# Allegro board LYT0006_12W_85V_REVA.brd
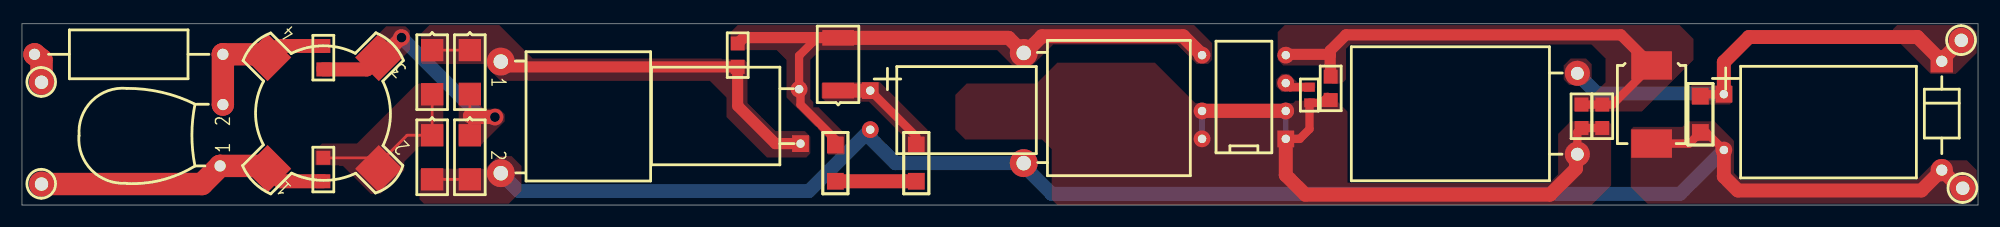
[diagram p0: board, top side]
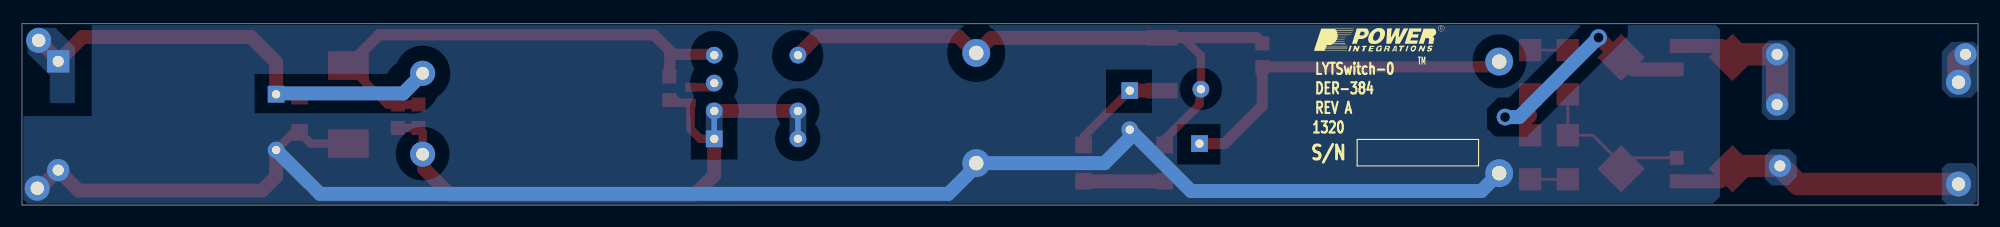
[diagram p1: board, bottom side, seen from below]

Outline 178.05 x 16.5 mm; copper layers: TOP, BOTTOM. Coordinates in mm from the lower left corner of the outline.
Outline path: 0,16.5 178.05,16.5 178.05,0 0,0 0,16.5

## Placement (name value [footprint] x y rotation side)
C1  100 nF  [PINPCAPRAD500X260400040H]  43.56 13.09 270 top
C2  330 nF  [PI_NP_CAPRAD512X299LS394D040_H]  91.19 13.85 270 top
C3  100 nF  [PISMC0603]  117.2 10.72 270 top
C4  22 uF  [PISMC0805]  119.13 11.69 270 top
C5  68 uF  [PIPOLCAPCLYD395X630LS200030H]  154.91 10.09 270 bottom
C6  1.0 uF  [PIPOLCAPCLYD320LS140030H]  77.22 8.64 270 top
D1  S1ML  [PISMDSMA]  37.34 14.1 270 top
D2  S1ML  [PISMDSMA]  40.77 14.1 270 top
D3  S1ML  [PISMDSMA]  37.34 6.35 270 top
D4  S1ML  [PISMDSMA]  40.77 6.35 270 top
D5  STTH2R06S  [PISMDO214AB12]  148.34 12.7 270 top
D6  DL4005-13-F  [PISMDMLL4112]  74.3 10.42 90 top
J1  PCB Terminal 22 AWG  [PI_HOLE_22AWG]  1.78 1.91 0 top
J2  PCB Terminal 22 AWG  [PI_HOLE_22AWG]  1.78 11.18 0 top
J3  PCB Terminal 22 AWG  [PI_HOLE_22AWG]  176.53 14.99 0 top
J4  PCB Terminal 22 AWG  [PI_HOLE_22AWG]  176.66 1.53 0 top
L1  10 mH  [PI_SM_IND_RENCO_RL9250]  22.35 3.31 135 top
L2  10 mH  [PI_CHOKE_450HX375LS197D030_H]  71.25 5.59 90 top
L3  3.3mh  [PI_CHOKE_710HX450LS290D046_H]  141.58 4.63 90 top
NOREF  -  []  0.64 0 90 top
NOREF#2  -  []  0 16.5 0 top
NOREF#3  -  []  -150.78 54.24 0 top
NOREF#4  -  []  -228.6 -144.78 0 top
NOREF#5  -  []  60.45 13.97 180 bottom
R1  4.7 k  [PISMR0805]  65.15 12.58 90 top
R2  30.1  [PISMR0805]  141.96 7.01 90 top
R3  30.1  [PISMR0805]  143.84 7.01 90 top
R4  180 k  [PISMR1206]  74.04 5.47 270 top
R5  180 k  [PISMR1206]  81.41 2.16 90 top
R6  22 k  [PISMR0805]  27.43 2.16 90 top
R7  1 M  [PISMR1206]  152.78 9.91 270 top
R8  22 k  [PISMR0805]  27.43 14.48 270 top
RF1  4.7  [PI12WVRESD180LS200D040]  18.29 13.72 180 top
RV1  275 Vac  [PI_DISC_354X220_LS220X10_040_H]  18.03 3.56 90 top
U1  LYT0006PN  [PIICDIP8B]  115.04 6.02 90 top
VR1  1N4764A  [PIDV200X110X040DO41]  174.75 13.09 270 top

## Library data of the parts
C1 = CAP NP: alternate symbols: (pinpcaprad500x260400040h)
C2 = CAP NP: alternate symbols: (pi_np_caprad512x299ls394d040_h)
C3 C4 = CAP NP
C5 = CAP POL: alternate symbols: (pipolcapclyd395x630ls200030h)
C6 = CAP POL: alternate symbols: (pipolcapclyd320ls140030h)
D1-D6 = DIODE
J1-J4 = TERM_1PIN
L1 = INDUCTOR_4P_revD
L2 L3 = INDUCTOR
R1-R8 = R
RF1 = R: alternate symbols: (pi12wvresd180ls250d040,pi12wresd180ls675d040)
RV1 = VARISTOR
U1 = LNK30X_HS_0
VR1 = DIODE_ZENER: alternate symbols: (pidax475x125040do41,pidv200x110x040do41wbead,pidax390x125040do41)

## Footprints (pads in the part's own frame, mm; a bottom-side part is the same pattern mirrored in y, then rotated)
PI12WVRESD180LS200D040
  round 2.032 hole 1.016: 1(0,0) 2(17.145,0)
PI_CHOKE_450HX375LS197D030_H
  rect 1.524x1.524 hole 0.762: 1(0,0.381)
  round 1.524 hole 0.762: 2(4.953,0.508)
PI_CHOKE_710HX450LS290D046_H
  round 2.286 hole 1.168: 1(0,0) 2(7.366,0)
PI_DISC_354X220_LS220X10_040_H
  round 2.032 hole 1.016: 1(0,0) 2(5.588,-0.254)
PI_HOLE_22AWG
  round 2.286 hole 1.219: 1(0,0)
PI_NP_CAPRAD512X299LS394D040_H
  round 2.54 hole 1.321: 1(0,0) 2(10.033,0)
PI_SM_IND_RENCO_RL9250
  rect 3.048x3.048 smd: 1(0,0) 2(-7.163,-7.163) 3(0,-14.326) 4(7.163,-7.163)
PIDV200X110X040DO41
  rect 2.032x2.032 hole 1.016: 1(0,0)
  round 2.032 hole 1.016: 2(9.906,0)
PIICDIP8B
  rect 1.524x1.524 hole 0.762: 1(0,0)
  round 1.524 hole 0.762: 2(2.54,0) 3(5.08,0) 4(7.62,0) 5(7.62,7.62) 7(2.54,7.62) 8(0,7.62)
PINPCAPRAD500X260400040H
  round 2.54 hole 1.321: 1(0.025,0.025) 2(10.185,0.025)
PIPOLCAPCLYD320LS140030H
  rect 1.524x1.524 hole 0.762: 1(-1.778,0)
  round 1.524 hole 0.762: 2(1.778,0)
PIPOLCAPCLYD395X630LS200030H
  rect 1.524x1.524 hole 0.762: 1(0,0)
  round 1.524 hole 0.762: 2(5.08,0)
PISMC0603
  rect 0.813x0.965 smd: 1(0,0) 2(1.422,0)
PISMC0805
  rect 1.27x1.27 smd: 1(0,0) 2(2.134,0)
PISMDMLL4112
  rect 1.422x2.896 smd: 1(0,0) 2(4.801,0)
PISMDO214AB12
  rect 2.591x3.708 smd: 1(0,0) 2(7.112,0)
PISMDSMA
  rect 2.032x2.032 smd: 1(0,0) 2(4.013,0)
PISMR0805
  rect 1.27x1.27 smd: 1(0,0) 2(2.134,0)
PISMR1206
  rect 1.524x1.524 smd: 1(0,0) 2(3.302,0)

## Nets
SOURCE: C3.2 C4.2 L3.1 R2.1 R3.1 U1.1(SOURCE) U1.2 U1.7 U1.8
N40967: C1.1 D1.1 D2.1 L2.1 R1.1
N41017: C1.2 C2.2 C5.2 C6.2 D3.2 D4.2 D5.2 J4.1 R7.2 VR1.2
N41033: C2.1 D6.2 L2.2 R1.2 R4.1 U1.5(D)
N41049: C4.1 D5.1 R2.2 R3.2 U1.4(FB)
N41137: C5.1 J3.1 L3.2 R7.1 VR1.1
N41161: J1.1 L1.1 R6.1 RV1.1
N41165: L1.4 R8.1 RF1.1 RV1.2
N41233: C3.1 U1.3(BP)
N41297: J2.1 RF1.2
N42430: D2.2 D4.1 L1.3 R8.2
N42434: D1.2 D3.1 L1.2 R6.2
N45514: R4.2 R5.1
N45535: C6.1 D6.1 R5.2

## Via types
v1: diameter 1.524, hole 0.889, TOP to BOTTOM, 2 vias

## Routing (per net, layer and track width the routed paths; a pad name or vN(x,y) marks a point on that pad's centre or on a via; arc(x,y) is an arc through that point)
SOURCE: length 57.6
  TOP w0.508: C4.2 118.87,9.3 118.31,9.3
  TOP w0.762: L3.1 141.58,6.63 R2.1 R3.1 ; 118.85,9.84 118.31,9.3 C3.2 117.2,6.91 116.31,6.02 U1.1
  TOP w1.27: L3.1 141.45,4.5 141.45,3.31 139.09,0.94 116.81,0.94 115.04,2.72 U1.1 ; U1.7 U1.2
  BOTTOM w0.508: U1.8 U1.7 ; U1.1 U1.2
N40967: length 35.9
  TOP w0.254: D1.1 D2.1
  TOP w0.762: 44.07,12.58 C1.1
  TOP w1.016: 44.07,12.58 R1.1 65.15,9.02 68.58,5.59 L2.1
N41017: length 156.2
  TOP w0.254: D3.2 D4.2
  TOP w0.762: C5.2 153.31,6.61 R7.2 151.76,5.59 D5.2
  TOP w1.27: C5.2 154.91,2.6 156.18,1.33 172.9,1.33 174.75,3.18 176.4,1.53 J4.1
  BOTTOM w1.27: C5.2 150.93,1.02 93.73,1.02 91.19,3.56 C2.2 79.5,3.81 77.22,6.1 C6.2 71.63,1.27 45.21,1.27 C1.2
N41033: length 56.2
  TOP w0.762: 72.39,15.24 70.74,13.59 L2.2 70.87,10.42 70.87,9.15 74.04,5.97 R4.1
  TOP w1.016: R1.2 65.68,15.24 74.27,15.24 D6.2
  TOP w1.27: D6.2 89.81,15.22 C2.1 91.31,13.85 92.84,15.37 105.69,15.37 U1.5
N41049: length 45.4
  TOP w0.762: D5.1 144.78,9.15 R3.2 R2.2
  TOP w1.016: C4.1 119.13,12.58 119.08,12.62 119.08,13.64 ; U1.4 115.11,13.72 119,13.72 119.08,13.64 ; D5.1 145.54,15.5 120.52,15.5 119.08,14.06 119.08,13.64
N41137: length 43.6
  TOP w0.762: R7.1 152.96,10.09 C5.1
  TOP w1.27: C5.1 154.91,13.01 157.2,15.3 172.54,15.3 VR1.1 174.75,13.21 J3.1
  BOTTOM w1.27: L3.2 141.58,11.94 143.36,10.16 154.84,10.16 C5.1
N41161: length 26.9
  TOP w1.27: L1.1 23.5,2.16 R6.1
  TOP w2.032: J1.1 16.38,1.91 RV1.1 22.1,3.56 L1.1
N41165: length 14.3
  TOP w1.27: L1.4 23.4,14.48 R8.1
  TOP w2.032: L1.4 22.07,13.72 RF1.1 RV1.2
N41233: length 2.3
  TOP w0.762: C3.1 115.42,10.72 U1.3
N41297: length 2.8
  TOP w2.032: J2.1 1.78,13.21 RF1.2
N42430: length 25.9
  TOP w0.254: D2.2 D4.1
  TOP w1.27: v1(43.05,8.01) 40.89,8.01 40.77,8.13 ; v1(34.54,15.24) 32.74,13.44 L1.3 31.39,12.35 R8.2
  BOTTOM w1.27: v1(43.05,8.01) 41.78,8.01 v1(34.54,15.24)
N42434: length 15.6
  TOP w0.254: R6.2 31.49,4.3 L1.2 32.48,3.78 35.05,6.35 D3.1 D1.2
N45514: length 7.4
  TOP w1.27: R4.2 R5.1
N45535: length 9.6
  TOP w0.762: C6.1 81.41,6.23 R5.2
  TOP w1.27: C6.1 D6.1

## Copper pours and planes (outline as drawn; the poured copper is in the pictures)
SOURCE on TOP: 115.7,9.28 106.81,9.28 103.12,12.96 94.23,12.96 92.33,11.05 85.98,11.05 84.96,10.04 84.96,6.86 85.85,5.97 92.84,5.97 93.73,5.08 93.73,0.51 94.23,0 119.13,0 120.65,1.53 120.65,8.51 118.87,10.29 118.49,10.29 117.86,9.66 116.08,9.66
SOURCE on TOP: 144.4,7.62 140.97,7.62 139.83,6.48 139.83,2.8 139.06,2.04 120.65,2.04 120.52,2.16 119.38,2.16 118.62,1.4 118.62,0.51 119.13,0 142.88,0 144.65,1.78 144.65,7.37
SOURCE on BOTTOM: 115.49,9.3 114.66,9.3 114.27,8.92 114.27,5.26 115.77,5.26 115.8,5.29 115.8,9
SOURCE on BOTTOM: 107.87,9.25 107.04,9.25 106.65,8.87 106.65,5.69 107.04,5.31 107.72,5.31 108.18,5.77 108.18,8.95
N40967 on TOP: 36.32,12.96 36.32,15.63 37.08,16.39 43.43,16.39 46.48,13.34 65.66,13.34 66.04,12.96 66.04,9.28 68.58,6.74 71.25,6.74 71.75,6.23 71.75,4.7 71.37,4.32 67.82,4.32 64.14,8.01 64.14,9.78 62.61,11.31 43.56,11.31 42.04,12.83 36.45,12.83
N41017 on TOP: 146.43,1.66 146.43,6.86 146.69,7.12 151.13,7.12 151.64,7.62 154.05,7.62 155.83,5.85 155.83,2.93 156.46,2.29 172.47,2.29 174.24,4.07 177.04,4.07 177.93,3.18 177.93,0.77 177.29,0.13 147.96,0.13
N41017 on TOP: 36.32,3.31 42.16,3.31 43.31,4.45 44.58,4.45 45.47,3.56 45.47,1.27 44.32,0.13 36.58,0.13 36.2,0.51 36.2,3.18
N41017 on BOTTOM: 24.13,0.13 23.5,0.77 23.5,16.01 23.88,16.39 31.88,16.39 31.88,15.37 41.02,6.23 43.94,6.23 44.7,6.99 44.7,8.77 43.69,9.78 42.67,9.78 36.07,16.39 90.46,16.39 91.19,11.2 91.92,16.39 171.7,16.39 171.7,8.11 177.93,8.11 177.93,0.51 177.55,0.13 ; 9 cut-outs
N41033 on TOP: 64.52,14.1 64.52,15.75 65.15,16.39 106.68,16.39 108.33,14.74 108.33,13.21 107.95,12.83 106.93,12.83 105.16,14.61 93.85,14.61 91.82,12.58 90.3,12.58 88.77,14.1 72.64,14.1 71.75,13.21 71.75,9.66 74.93,6.48 74.93,4.7 74.8,4.58 73.41,4.58 73.28,4.7 73.28,6.1 69.6,9.78 69.6,13.21 68.71,14.1
N41049 on TOP: 114.3,13.21 114.3,15.75 114.94,16.39 150.88,16.39 152.15,15.12 152.15,13.21 147.45,8.51 141.35,8.51 141.22,8.64 141.22,9.91 141.48,10.16 143.13,10.16 144.15,11.18 144.15,13.34 142.88,14.61 120.9,14.61 120.52,14.23 120.52,11.43 120.14,11.05 118.49,11.05 118.49,12.32 118.11,12.7 114.81,12.7
N41137 on TOP: 170.31,16.01 170.69,16.39 177.29,16.39 177.93,15.75 177.93,13.85 176.02,11.94 173.74,11.94 170.31,15.37
N41137 on TOP: 142.37,13.34 140.97,13.34 140.34,12.7 140.34,11.43 140.84,10.93 142.24,10.93 142.88,11.56 142.88,12.83
N41137 on TOP: 152.02,9.15 155.45,9.15 155.7,9.4 155.7,10.8 155.57,10.93 152.02,10.93 151.89,10.8 151.89,9.28
N41137 on BOTTOM: 173.23,9.28 173.23,14.36 175.01,16.13 176.78,16.13 177.55,15.37 177.55,13.85 175.51,11.82 175.51,9.4 175.39,9.28
N41161 on BOTTOM: 2.79,3.81 0.51,3.81 0.13,3.43 0.13,0.39 0.51,0 2.79,0 3.3,0.51 3.3,3.31
N41161 on BOTTOM: 18.8,5.08 17.14,5.08 16.51,4.45 16.51,2.54 17.27,1.78 18.8,1.78 19.43,2.42 19.43,4.45
N41165 on BOTTOM: 16.64,8.39 16.64,14.23 17.4,14.99 19.05,14.99 19.68,14.36 19.68,8.39 19.05,7.75 17.27,7.75
N41233 on TOP: 114.68,11.94 115.32,11.94 116.08,11.18 117.73,11.18 117.73,10.29 114.68,10.29 114.17,10.8 114.17,11.43
N41297 on BOTTOM: 3.3,10.55 3.3,13.97 2.41,14.86 0.38,14.86 0,14.48 0,10.42 0.64,9.78 2.54,9.78
N42430 on TOP: 32.38,15.5 33.15,16.26 34.92,16.26 35.31,15.88 35.31,14.1 34.54,13.34
N42430 on TOP: 41.78,11.18 41.78,9.02 42.04,8.77 43.43,8.77 43.94,8.26 43.94,7.62 41.66,5.34 39.88,5.34 39.75,5.47 39.75,11.18
N42434 on TOP: 38.35,11.05 35.94,11.05 30.48,5.59 27.3,5.59 26.67,4.96 26.67,3.69 26.8,3.56 29.21,3.56 31.75,1.02 32.64,1.02 34.8,3.18 34.8,3.94 36.2,5.34 38.35,5.34
N45535 on TOP: 72.9,11.18 78.11,11.18 82.42,6.86 82.42,4.83 82.3,4.7 80.52,4.7 80.39,4.83 80.39,6.1 77.09,9.4 73.15,9.4 72.77,9.78 72.77,11.05

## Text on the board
Ref Des/Silkscreen Bottom: TM | LYTSwitch-0 | DER-384 | REV A | 1320 | S/N
PEN17: 13   MATERIAL FR4 COPPER 2oz THICKNESS 0.031" DOUBLE SIDED.
User.5: FIGURE | SIZE | 30.0 | 35.0 | 40.0 | 46.0 | 48.0 | 52.0 | DRILL CHART: TOP to BOTTOM | ALL UNITS ARE IN MILS | PLATED | QTY | 13 | 2 | 6 | 4
User.7: SLOT
